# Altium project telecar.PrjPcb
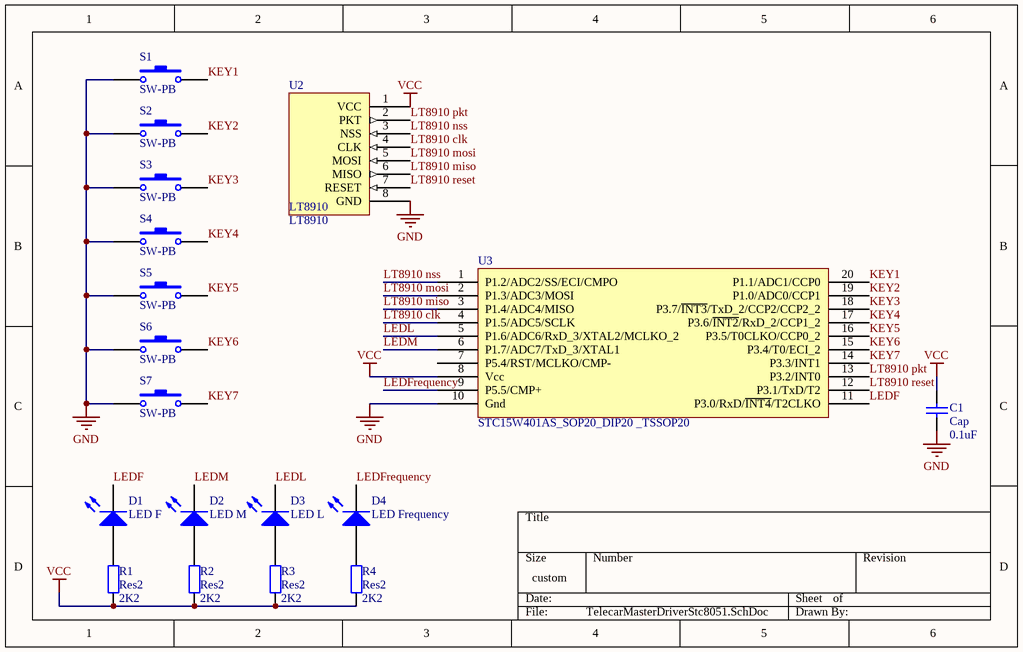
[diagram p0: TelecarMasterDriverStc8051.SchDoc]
2 sheets, 39 parts. Net scope: global (net labels, ports and power ports of the same name join across sheets).
Sheets:
  TelecarMasterDriverStc8051.SchDoc
  TelecarRemoteControlStc8051.SchDoc

## Sheet TelecarMasterDriverStc8051.SchDoc
size 190 x 120 mm; PageSetup: Record=PageOptions?CenterHorizontal=True?CenterVertical=True?PrintScale=0.67?XCorrection=1.00?YCorrection=1.00?PrintKind=1?BorderSize=5000000?LeftOffset=0?BottomOffset=0?Orientation=2?PaperLength=1000?PaperWidth=1000?Scale=100?PaperSource=7?PrintQuality=-4?MediaType=1?DitherType=10?PaperKind=A5?PrintScaleMode=1

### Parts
(Parts that share a designator on the sheet are numbered #1, #2 ... from top to bottom, then left to right.)
C1#1  Cap  value 0.1uF  [RAD-0.3]
D1#1  LED F  [LED-1]
D2#1  LED M  [LED-1]
D3#1  LED L  [LED-1]
D4#1  LED Frequency  [LED-1]
R1#1  Res2  value 2K2  [AXIAL-0.4]
R2#1  Res2  value 2K2  [AXIAL-0.4]
R3#1  Res2  value 2K2  [AXIAL-0.4]
R4#1  Res2  value 2K2  [AXIAL-0.4]
S1#1  SW-PB  [SPST-2]
S2#1  SW-PB  [SPST-2]
S3  SW-PB  [SPST-2]
S4  SW-PB  [SPST-2]
S5  SW-PB  [SPST-2]
S6  SW-PB  [SPST-2]
S7  SW-PB  [SPST-2]
U2#1  LT8910
U3  STC15W401AS_SOP20_DIP20 _TSSOP20  [TSSOP20]

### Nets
GND: C1#1.1 S1#1.1 S2#1.1 S3.1 S4.1 S5.1 S6.1 S7.1 U2#1.8(GND) U3.10(Gnd)
VCC: C1#1.2 R1#1.1 R2#1.1 R3#1.1 R4#1.1 U2#1.1(VCC) U3.8(Vcc)
KEY1: S1#1.2 U3.20(P1.1/ADC1/CCP0)
KEY2: S2#1.2 U3.19(P1.0/ADC0/CCP1)
KEY3: S3.2 U3.18(P3.7/~{INT3}/TxD_2/CCP2/CCP2_2)
KEY4: S4.2 U3.17(P3.6/~{INT2}/RxD_2/CCP1_2)
KEY5: S5.2 U3.16(P3.5/T0CLKO/CCP0_2)
KEY6: S6.2 U3.15(P3.4/T0/ECI_2)
KEY7: S7.2 U3.14(P3.3/INT1)
LEDF: D1#1.2(K) U3.11(P3.0/RxD/~{INT4}/T2CLKO)
LEDFrequency: D4#1.2(K) U3.9(P5.5/CMP+)
LEDL: D3#1.2(K) U3.5(P1.6/ADC6/RxD_3/XTAL2/MCLKO_2)
LEDM: D2#1.2(K) U3.6(P1.7/ADC7/TxD_3/XTAL1)
LT8910 clk: U2#1.4(CLK) U3.4(P1.5/ADC5/SCLK)
LT8910 miso: U2#1.6(MISO) U3.3(P1.4/ADC4/MISO)
LT8910 mosi: U2#1.5(MOSI) U3.2(P1.3/ADC3/MOSI)
LT8910 nss: U2#1.3(NSS) U3.1(P1.2/ADC2/SS/ECI/CMPO)
LT8910 pkt: U2#1.2(PKT) U3.13(P3.2/INT0)
LT8910 reset: U2#1.7(RESET) U3.12(P3.1/TxD/T2)
NetD1#1_1: D1#1.1(A) R1#1.2
NetD2#1_1: D2#1.1(A) R2#1.2
NetD3#1_1: D3#1.1(A) R3#1.2
NetD4#1_1: D4#1.1(A) R4#1.2

Not connected (* = marked no-connect by the designer): U3 7(P5.4/RST/MCLKO/CMP-)

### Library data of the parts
C1#1 = Cap: Capacitor
D1#1 D2#1 D3#1 D4#1 = LED1: Typical RED GaAs LED
R1#1 R2#1 R3#1 R4#1 = Res2: Resistor
S1#1 S2#1 S3-S7 = SW-PB: Switch

## Sheet TelecarRemoteControlStc8051.SchDoc
size 190 x 120 mm
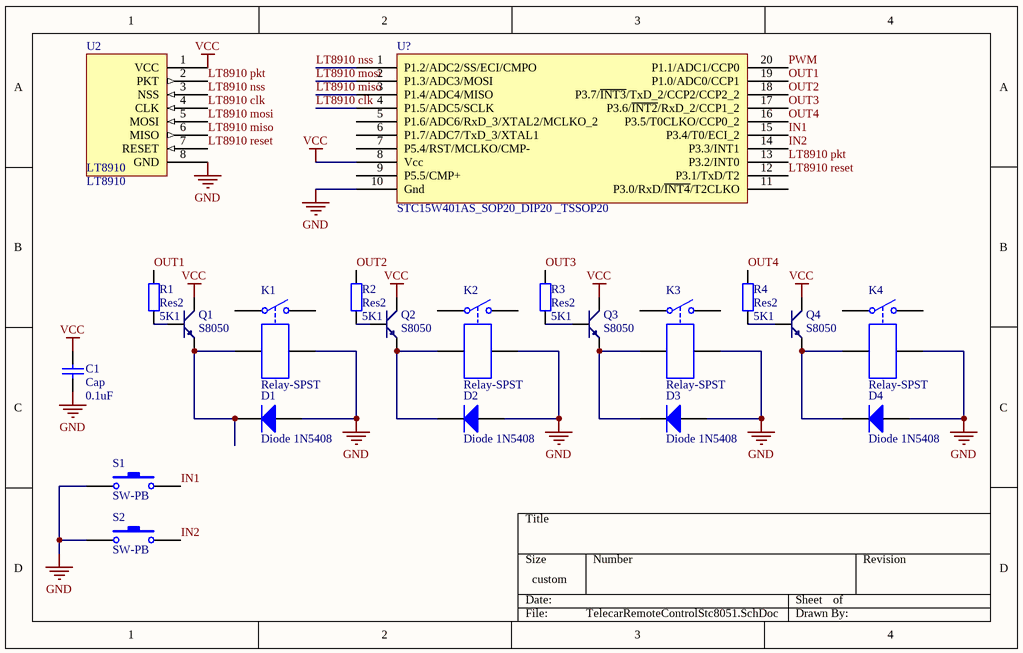
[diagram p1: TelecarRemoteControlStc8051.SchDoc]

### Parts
(Parts that share a designator on the sheet are numbered #1, #2 ... from top to bottom, then left to right.)
C1#2  Cap  value 0.1uF  [RAD-0.3]
D1#2  Diode 1N5408  [DIO18.84-9.6x5.6]
D2#2  Diode 1N5408  [DIO18.84-9.6x5.6]
D3#2  Diode 1N5408  [DIO18.84-9.6x5.6]
D4#2  Diode 1N5408  [DIO18.84-9.6x5.6]
K1  Relay-SPST  [DIP-P4]
K2  Relay-SPST  [DIP-P4]
K3  Relay-SPST  [DIP-P4]
K4  Relay-SPST  [DIP-P4]
Q1  S8050  [SOT-23R]
Q2  S8050  [SOT-23R]
Q3  S8050  [SOT-23R]
Q4  S8050  [SOT-23R]
R1#2  Res2  value 5K1  [AXIAL-0.4]
R2#2  Res2  value 5K1  [AXIAL-0.4]
R3#2  Res2  value 5K1  [AXIAL-0.4]
R4#2  Res2  value 5K1  [AXIAL-0.4]
S1#2  SW-PB  [SPST-2]
S2#2  SW-PB  [SPST-2]
U2#2  LT8910
U?  STC15W401AS_SOP20_DIP20 _TSSOP20  [TSSOP20]

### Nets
GND: C1#2.1 D1#2.1(A) D2#2.1(A) D3#2.1(A) D4#2.1(A) K1.4 K2.4 K3.4 K4.4 S1#2.1 S2#2.1 U2#2.8(GND) U?.10(Gnd)
VCC: C1#2.2 Q1.3(C) Q2.3(C) Q3.3(C) Q4.3(C) U2#2.1(VCC) U?.8(Vcc)
IN1: S1#2.2 U?.15(P3.4/T0/ECI_2)
IN2: S2#2.2 U?.14(P3.3/INT1)
LT8910 clk: U2#2.4(CLK) U?.4(P1.5/ADC5/SCLK)
LT8910 miso: U2#2.6(MISO) U?.3(P1.4/ADC4/MISO)
LT8910 mosi: U2#2.5(MOSI) U?.2(P1.3/ADC3/MOSI)
LT8910 nss: U2#2.3(NSS) U?.1(P1.2/ADC2/SS/ECI/CMPO)
LT8910 pkt: U2#2.2(PKT) U?.13(P3.2/INT0)
LT8910 reset: U2#2.7(RESET) U?.12(P3.1/TxD/T2)
OUT1: R1#2.2 U?.19(P1.0/ADC0/CCP1)
OUT2: R2#2.2 U?.18(P3.7/~{INT3}/TxD_2/CCP2/CCP2_2)
OUT3: R3#2.2 U?.17(P3.6/~{INT2}/RxD_2/CCP1_2)
OUT4: R4#2.2 U?.16(P3.5/T0CLKO/CCP0_2)
PWM: U?.20(P1.1/ADC1/CCP0)
NetD1#2_2: D1#2.2(K) K1.3 Q1.1(E)
NetD2#2_2: D2#2.2(K) K2.3 Q2.1(E)
NetD3#2_2: D3#2.2(K) K3.3 Q3.1(E)
NetD4#2_2: D4#2.2(K) K4.3 Q4.1(E)
NetQ1_2: Q1.2(B) R1#2.1
NetQ2_2: Q2.2(B) R2#2.1
NetQ3_2: Q3.2(B) R3#2.1
NetQ4_2: Q4.2(B) R4#2.1

Not connected (* = marked no-connect by the designer): K1 1 2; K2 1 2; K3 1 2; K4 1 2; U? 5(P1.6/ADC6/RxD_3/XTAL2/MCLKO_2) 6(P1.7/ADC7/TxD_3/XTAL1) 7(P5.4/RST/MCLKO/CMP-) 9(P5.5/CMP+) 11(P3.0/RxD/~{INT4}/T2CLKO)

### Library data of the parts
C1#2 = Cap: Capacitor
D1#2 D2#2 D3#2 D4#2 = Diode 1N5408: 3 Amp Medium Power Silicon Rectifier Diode
K1-K4 = Relay-SPST: Single-Pole Single-Throw Relay
Q1-Q4 = NPN: 8050/BCW846/BCW847
R1#2 R2#2 R3#2 R4#2 = Res2: Resistor
S1#2 S2#2 = SW-PB: Switch

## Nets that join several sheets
GND: TelecarMasterDriverStc8051 (10 pins), TelecarRemoteControlStc8051 (13 pins)
VCC: TelecarMasterDriverStc8051 (7 pins), TelecarRemoteControlStc8051 (7 pins)
LT8910 clk: TelecarMasterDriverStc8051 (U2#1.4 U3.4), TelecarRemoteControlStc8051 (U2#2.4 U?.4)
LT8910 miso: TelecarMasterDriverStc8051 (U2#1.6 U3.3), TelecarRemoteControlStc8051 (U2#2.6 U?.3)
LT8910 mosi: TelecarMasterDriverStc8051 (U2#1.5 U3.2), TelecarRemoteControlStc8051 (U2#2.5 U?.2)
LT8910 nss: TelecarMasterDriverStc8051 (U2#1.3 U3.1), TelecarRemoteControlStc8051 (U2#2.3 U?.1)
LT8910 pkt: TelecarMasterDriverStc8051 (U2#1.2 U3.13), TelecarRemoteControlStc8051 (U2#2.2 U?.13)
LT8910 reset: TelecarMasterDriverStc8051 (U2#1.7 U3.12), TelecarRemoteControlStc8051 (U2#2.7 U?.12)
